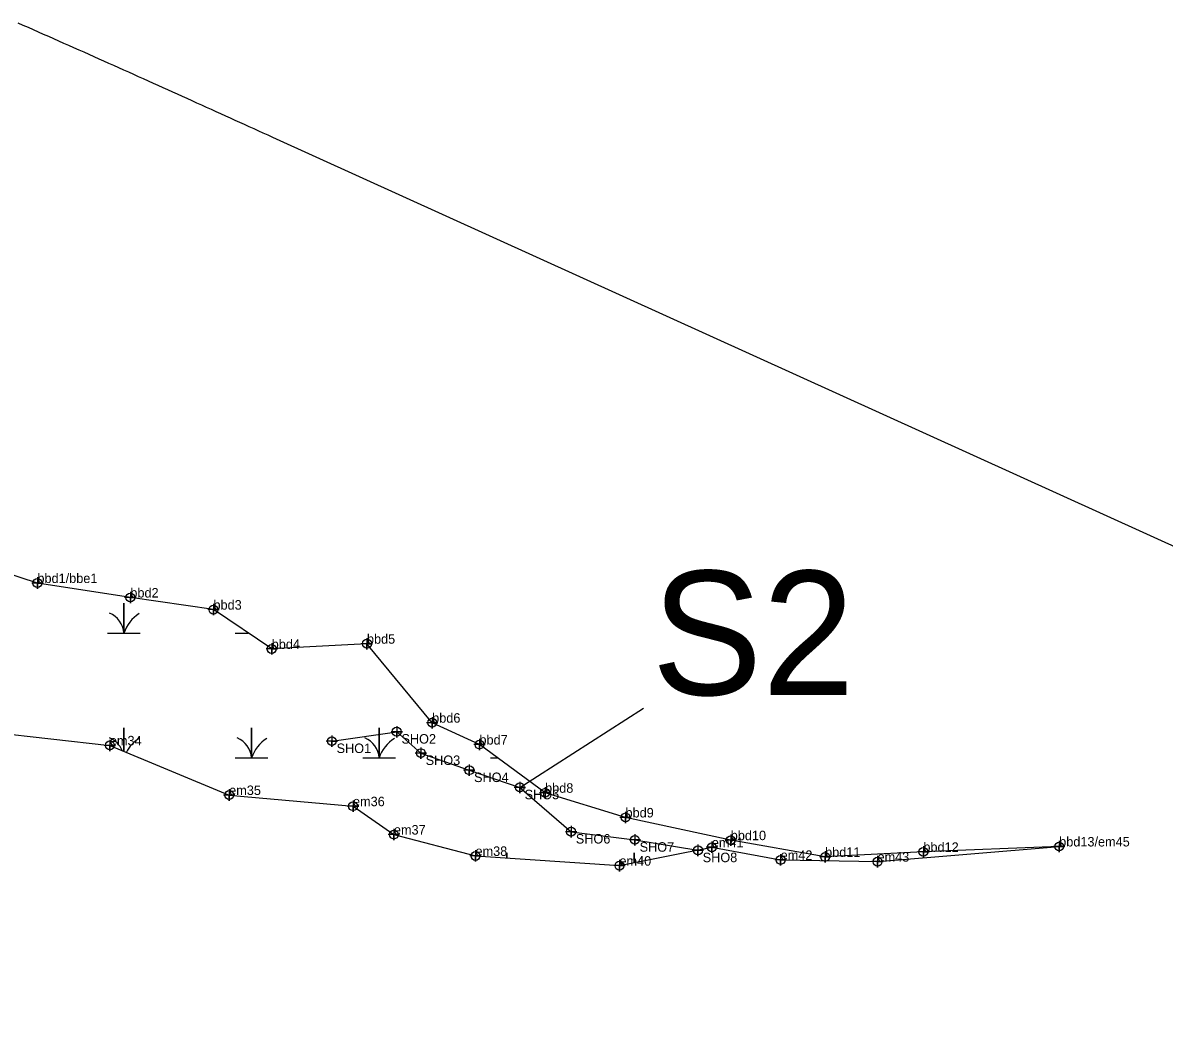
# Model space of a CAD drawing. Extents: x 2071991 to 2268989, y 436479 to 469629.
# Drawn here: x 2245567 to 2246168, y 440471 to 440993 of the extents above; entities that cross this region are included whole.
import ezdxf

# ---------------------------------------------------------------- set-up
doc = ezdxf.new("R2010")
doc.units = 0
for name, color, linetype in [('approx_PSA', 7, 'Continuous'), ('Default', 7, 'Continuous'), ('Exist Environmental Wetland Boundary', 7, 'Continuous'), ('Exist Environmental Wetland Boundary Cogo Comment', 7, 'Continuous'), ('Exist Environmental Wetland Boundary Cogo Point CELL', 7, 'Continuous'), ('Exist Hydro Jurisdictional Stream or Body of Water NEU Mitigable', 7, 'Continuous'), ('Exist Hydro Jurisdictional Stream or Body of Water NEU Mitigable Cogo Comment', 7, 'Continuous'), ('Exist Hydro Jurisdictional Stream or Body of Water NEU Mitigable Cogo Point CELL', 7, 'Continuous'), ('Exist Hydro Jurisdictional Stream or Body of Water NEU NonMitigable', 7, 'Continuous'), ('Exist Hydro Jurisdictional Stream or Body of Water NEU NonMitigable Cogo Comment', 7, 'Continuous'), ('Exist Hydro Jurisdictional Stream or Body of Water NEU NonMitigable Cogo Point CELL', 7, 'Continuous'), ('Exist Hydro Swamp or Marsh', 7, 'Continuous')]:
    doc.layers.add(name, color=color, linetype=linetype)

msp = doc.modelspace()

# ---------------------------------------------------------------- linework, layer by layer
at = {"layer": 'approx_PSA'}
for p, q in [((2245564.02, 440992.9), (2245566.68, 440991.73)), ((2245566.68, 440991.73), (2245569.42, 440990.53)), ((2245569.42, 440990.53), (2245572.08, 440989.35)), ((2245572.08, 440989.35), (2245574.78, 440988.17)), ((2245574.78, 440988.17), (2245577.41, 440987.01)), ((2245577.41, 440987.01), (2245580.15, 440985.8)), ((2245580.15, 440985.8), (2245582.84, 440984.6)), ((2245582.84, 440984.6), (2245585.47, 440983.44)), ((2245585.47, 440983.44), (2245588.13, 440982.26)), ((2245588.13, 440982.26), (2245590.79, 440981.08)), ((2245590.79, 440981.08), (2245593.41, 440979.92)), ((2245593.41, 440979.92), (2245596.07, 440978.73)), ((2245596.07, 440978.73), (2245598.76, 440977.53)), ((2245598.76, 440977.53), (2245601.34, 440976.38)), ((2245601.34, 440976.38), (2245604.04, 440975.18)), ((2245604.04, 440975.18), (2245606.66, 440974.01)), ((2245606.66, 440974.01), (2245609.16, 440972.89)), ((2245609.16, 440972.89), (2245611.85, 440971.69)), ((2245611.85, 440971.69), (2245614.47, 440970.51)), ((2245614.47, 440970.51), (2245617.1, 440969.34)), ((2245617.1, 440969.34), (2245619.71, 440968.17)), ((2245619.71, 440968.17), (2245622.25, 440967.03)), ((2245622.25, 440967.03), (2245624.87, 440965.85)), ((2245624.87, 440965.85), (2245627.48, 440964.67)), ((2245627.48, 440964.67), (2245630.1, 440963.5)), ((2245630.1, 440963.5), (2245632.64, 440962.35)), ((2245632.64, 440962.35), (2245635.22, 440961.19)), ((2245635.22, 440961.19), (2245637.79, 440960.03)), ((2245637.79, 440960.03), (2245640.33, 440958.88)), ((2245640.33, 440958.88), (2245642.87, 440957.74)), ((2245642.87, 440957.74), (2245645.45, 440956.57)), ((2245645.45, 440956.57), (2245647.99, 440955.43)), ((2245647.99, 440955.43), (2245650.56, 440954.26)), ((2245650.56, 440954.26), (2245653.1, 440953.12)), ((2245653.1, 440953.12), (2245655.64, 440951.97)), ((2245655.64, 440951.97), (2245658.21, 440950.8)), ((2245658.21, 440950.8), (2245660.68, 440949.69)), ((2245660.68, 440949.69), (2245663.25, 440948.52)), ((2245663.25, 440948.52), (2245665.79, 440947.37)), ((2245665.79, 440947.37), (2245668.25, 440946.25)), ((2245668.25, 440946.25), (2245670.82, 440945.09)), ((2245670.82, 440945.09), (2245673.32, 440943.95)), ((2245673.32, 440943.95), (2245675.79, 440942.83)), ((2245675.79, 440942.83), (2245678.28, 440941.7)), ((2245678.28, 440941.7), (2245680.74, 440940.58)), ((2245680.74, 440940.58), (2245683.28, 440939.43)), ((2245683.28, 440939.43), (2245685.78, 440938.3)), ((2245685.78, 440938.3), (2245688.24, 440937.18)), ((2245688.24, 440937.18), (2245690.74, 440936.05)), ((2245690.74, 440936.05), (2245693.12, 440934.96)), ((2245693.12, 440934.96), (2245695.62, 440933.83)), ((2245695.62, 440933.83), (2245698.11, 440932.7)), ((2245698.11, 440932.7), (2245698.16, 440932.68)), ((2245698.16, 440932.68), (2248718.76, 439560.51))]:
    msp.add_line(p, q, dxfattribs=at)
at = {"layer": 'Default'}
msp.add_line((2245828.45, 440590.1), (2245893.65, 440631.88), dxfattribs=at)
at = {"layer": 'Exist Environmental Wetland Boundary'}
for points in [[(2245939.52, 440562.28), (2245884.1, 440574.26), (2245841.74, 440587.26), (2245807.16, 440612.66), (2245782.26, 440624.17), (2245747.91, 440665.78), (2245697.75, 440663.04), (2245667.07, 440683.74), (2245623.29, 440690.13), (2245574.34, 440697.76), (2245536.56, 440709.98)], [(2245550.2, 440619.27), (2245612.5, 440612.22), (2245675.34, 440586.07), (2245740.56, 440580.18), (2245762.1, 440565.24), (2245805.08, 440553.99), (2245880.9, 440548.86), (2245929.55, 440558.54)]]:
    msp.add_lwpolyline(points, dxfattribs=at)
at = {"layer": 'Exist Environmental Wetland Boundary Cogo Point CELL'}
for points in [[(2245574.34, 440700.76), (2245574.34, 440694.76), (2245574.34, 440697.76), (2245577.34, 440697.76), (2245571.34, 440697.76)], [(2245623.29, 440693.13), (2245623.29, 440687.13), (2245623.29, 440690.13), (2245626.29, 440690.13), (2245620.29, 440690.13)], [(2245667.07, 440686.74), (2245667.07, 440680.74), (2245667.07, 440683.74), (2245670.07, 440683.74), (2245664.07, 440683.74)], [(2245697.75, 440666.04), (2245697.75, 440660.04), (2245697.75, 440663.04), (2245700.75, 440663.04), (2245694.75, 440663.04)], [(2245747.91, 440668.78), (2245747.91, 440662.78), (2245747.91, 440665.78), (2245750.91, 440665.78), (2245744.91, 440665.78)], [(2245782.26, 440627.17), (2245782.26, 440621.17), (2245782.26, 440624.17), (2245785.26, 440624.17), (2245779.26, 440624.17)], [(2245612.5, 440615.22), (2245612.5, 440609.22), (2245612.5, 440612.22), (2245615.5, 440612.22), (2245609.5, 440612.22)], [(2245807.16, 440615.66), (2245807.16, 440609.66), (2245807.16, 440612.66), (2245810.16, 440612.66), (2245804.16, 440612.66)], [(2245675.34, 440589.07), (2245675.34, 440583.07), (2245675.34, 440586.07), (2245678.34, 440586.07), (2245672.34, 440586.07)], [(2245841.74, 440590.26), (2245841.74, 440584.26), (2245841.74, 440587.26), (2245844.74, 440587.26), (2245838.74, 440587.26)], [(2245740.56, 440583.18), (2245740.56, 440577.18), (2245740.56, 440580.18), (2245743.56, 440580.18), (2245737.56, 440580.18)], [(2245884.1, 440577.26), (2245884.1, 440571.26), (2245884.1, 440574.26), (2245887.1, 440574.26), (2245881.1, 440574.26)], [(2245762.1, 440568.24), (2245762.1, 440562.24), (2245762.1, 440565.24), (2245765.1, 440565.24), (2245759.1, 440565.24)], [(2245805.08, 440556.99), (2245805.08, 440550.99), (2245805.08, 440553.99), (2245808.08, 440553.99), (2245802.08, 440553.99)], [(2245880.9, 440551.86), (2245880.9, 440545.86), (2245880.9, 440548.86), (2245883.9, 440548.86), (2245877.9, 440548.86)]]:
    msp.add_lwpolyline(points, dxfattribs=at)
for centre in [(2245574.34, 440697.76), (2245623.29, 440690.13), (2245667.07, 440683.74), (2245697.75, 440663.04), (2245747.91, 440665.78), (2245782.26, 440624.17), (2245612.5, 440612.22), (2245807.16, 440612.66), (2245675.34, 440586.07), (2245841.74, 440587.26), (2245740.56, 440580.18), (2245884.1, 440574.26), (2245762.1, 440565.24), (2245805.08, 440553.99), (2245880.9, 440548.86)]:
    msp.add_circle(centre, 2.34, dxfattribs=at)
at = {"layer": 'Exist Hydro Jurisdictional Stream or Body of Water NEU Mitigable'}
msp.add_lwpolyline([(2245729.41, 440614.45), (2245763.58, 440619.42), (2245776.32, 440608.14), (2245801.81, 440599.15), (2245828.45, 440590.1), (2245855.42, 440566.76), (2245889.02, 440562.45), (2245922.24, 440556.94), (2245929.55, 440558.54)], dxfattribs=at)
at = {"layer": 'Exist Hydro Jurisdictional Stream or Body of Water NEU Mitigable Cogo Point CELL'}
for points in [[(2245763.58, 440622.42), (2245763.58, 440616.42), (2245763.58, 440619.42), (2245766.58, 440619.42), (2245760.58, 440619.42)], [(2245729.41, 440617.45), (2245729.41, 440611.45), (2245729.41, 440614.45), (2245732.41, 440614.45), (2245726.41, 440614.45)], [(2245776.32, 440611.14), (2245776.32, 440605.14), (2245776.32, 440608.14), (2245779.32, 440608.14), (2245773.32, 440608.14)], [(2245801.81, 440602.15), (2245801.81, 440596.15), (2245801.81, 440599.15), (2245804.81, 440599.15), (2245798.81, 440599.15)], [(2245828.45, 440593.1), (2245828.45, 440587.1), (2245828.45, 440590.1), (2245831.45, 440590.1), (2245825.45, 440590.1)], [(2245855.42, 440569.76), (2245855.42, 440563.76), (2245855.42, 440566.76), (2245858.42, 440566.76), (2245852.42, 440566.76)], [(2245889.02, 440565.45), (2245889.02, 440559.45), (2245889.02, 440562.45), (2245892.02, 440562.45), (2245886.02, 440562.45)], [(2245922.24, 440559.94), (2245922.24, 440553.94), (2245922.24, 440556.94), (2245925.24, 440556.94), (2245919.24, 440556.94)]]:
    msp.add_lwpolyline(points, dxfattribs=at)
for centre in [(2245729.41, 440614.45), (2245763.58, 440619.42), (2245776.32, 440608.14), (2245801.81, 440599.15), (2245828.45, 440590.1), (2245855.42, 440566.76), (2245889.02, 440562.45), (2245922.24, 440556.94)]:
    msp.add_circle(centre, 2.34, dxfattribs=at)
at = {"layer": 'Exist Hydro Jurisdictional Stream or Body of Water NEU NonMitigable'}
msp.add_lwpolyline([(2245929.55, 440558.54), (2245965.81, 440551.89), (2246017.27, 440550.96), (2246112.51, 440558.96), (2246040.99, 440556.14), (2245989.23, 440553.47), (2245939.52, 440562.28)], dxfattribs=at)
at = {"layer": 'Exist Hydro Jurisdictional Stream or Body of Water NEU NonMitigable Cogo Point CELL'}
for points in [[(2245939.52, 440565.28), (2245939.52, 440559.28), (2245939.52, 440562.28), (2245942.52, 440562.28), (2245936.52, 440562.28)], [(2245929.55, 440561.54), (2245929.55, 440555.54), (2245929.55, 440558.54), (2245932.55, 440558.54), (2245926.55, 440558.54)], [(2245989.23, 440556.47), (2245989.23, 440550.47), (2245989.23, 440553.47), (2245992.23, 440553.47), (2245986.23, 440553.47)], [(2246040.99, 440559.14), (2246040.99, 440553.14), (2246040.99, 440556.14), (2246043.99, 440556.14), (2246037.99, 440556.14)], [(2246112.51, 440561.96), (2246112.51, 440555.96), (2246112.51, 440558.96), (2246115.51, 440558.96), (2246109.51, 440558.96)], [(2245965.81, 440554.89), (2245965.81, 440548.89), (2245965.81, 440551.89), (2245968.81, 440551.89), (2245962.81, 440551.89)], [(2246016.83, 440553.97), (2246016.83, 440547.97), (2246016.83, 440550.97), (2246019.83, 440550.97), (2246013.83, 440550.97)]]:
    msp.add_lwpolyline(points, dxfattribs=at)
for centre in [(2245939.52, 440562.28), (2245929.55, 440558.54), (2246040.99, 440556.14), (2246112.51, 440558.96), (2245965.81, 440551.89), (2245989.23, 440553.47), (2246016.83, 440550.97)]:
    msp.add_circle(centre, 2.34, dxfattribs=at)
at = {"layer": 'Exist Hydro Swamp or Marsh'}
for p, q in [((2245678.52, 440671.42), (2245685.32, 440671.42)), ((2245628.3, 440605.64), (2245628.52, 440605.64)), ((2245812.93, 440605.64), (2245816.71, 440605.64))]:
    msp.add_line(p, q, dxfattribs=at)
for points in [[(2245611.32, 440671.42), (2245619.92, 440671.42), (2245619.92, 440687.2), (2245619.92, 440671.42), (2245628.52, 440671.42)], [(2245619.92, 440609.13), (2245619.92, 440621.42), (2245619.92, 440609.13)], [(2245678.52, 440605.64), (2245687.12, 440605.64), (2245687.12, 440621.42), (2245687.12, 440605.64), (2245695.72, 440605.64)], [(2245745.72, 440605.64), (2245754.33, 440605.64), (2245754.33, 440621.42), (2245754.33, 440605.64), (2245762.93, 440605.64)], [(2245821.53, 440552.88), (2245821.53, 440555.64), (2245821.53, 440552.88)], [(2245888.73, 440550.42), (2245888.73, 440555.64), (2245888.73, 440550.42)]]:
    msp.add_lwpolyline(points, dxfattribs=at)
for centre, radius, start, end in [((2245607.65, 440670.54), 12.3, 4.14034, 67.53497), ((2245638.16, 440665.36), 19.22, 122.12745, 161.62219), ((2245607.65, 440604.76), 12.3, 22.76581, 67.53497), ((2245638.16, 440599.58), 19.22, 122.12745, 152.01726), ((2245674.86, 440604.76), 12.3, 4.14034, 67.53497), ((2245705.36, 440599.58), 19.22, 122.12745, 161.62219), ((2245742.06, 440604.76), 12.3, 4.14034, 67.53497), ((2245772.57, 440599.58), 19.22, 122.12745, 161.62219), ((2245876.47, 440538.98), 12.3, 57.14985, 67.53497)]:
    msp.add_arc(centre, radius, start, end, dxfattribs=at)

# ---------------------------------------------------------------- texts
at = {"layer": 'Default'}
msp.add_text('S2', height=65.34, dxfattribs=at).set_placement((2245897.84, 440638.8))
at = {"layer": 'Exist Environmental Wetland Boundary Cogo Comment'}
for s, p in [('bbd1/bbe1', (2245574.34, 440697.76)), ('bbd2', (2245623.29, 440690.13)), ('bbd3', (2245667.07, 440683.74)), ('bbd5', (2245747.91, 440665.78)), ('bbd4', (2245697.75, 440663.04)), ('bbd6', (2245782.26, 440624.17)), ('em34', (2245612.5, 440612.22)), ('bbd7', (2245807.16, 440612.66)), ('bbd8', (2245841.74, 440587.26)), ('em35', (2245675.34, 440586.07)), ('em36', (2245740.56, 440580.18)), ('bbd9', (2245884.1, 440574.26)), ('em37', (2245762.1, 440565.24)), ('em38', (2245805.08, 440553.99)), ('em40', (2245880.9, 440548.86))]:
    msp.add_text(s, height=5, dxfattribs=at).set_placement(p)
at = {"layer": 'Exist Hydro Jurisdictional Stream or Body of Water NEU Mitigable Cogo Comment'}
for s, p in [('SHO2', (2245766.08, 440613.17)), ('SHO1', (2245731.91, 440608.2)), ('SHO3', (2245778.82, 440601.89)), ('SHO4', (2245804.31, 440592.9)), ('SHO5', (2245830.95, 440583.85)), ('SHO6', (2245857.92, 440560.51)), ('SHO7', (2245891.52, 440556.2)), ('SHO8', (2245924.74, 440550.69))]:
    msp.add_text(s, height=5, dxfattribs=at).set_placement(p)
at = {"layer": 'Exist Hydro Jurisdictional Stream or Body of Water NEU NonMitigable Cogo Comment'}
for s, p in [('em41', (2245929.55, 440558.54)), ('bbd10', (2245939.52, 440562.28)), ('bbd13/em45', (2246112.51, 440558.96)), ('em42', (2245965.81, 440551.89)), ('bbd11', (2245989.23, 440553.47)), ('bbd12', (2246040.99, 440556.14)), ('em43', (2246016.83, 440550.97))]:
    msp.add_text(s, height=5, dxfattribs=at).set_placement(p)

doc.saveas('drawing.dxf')
